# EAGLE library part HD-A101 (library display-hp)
LED DISPLAY 1-character 7 segment, decimal point right
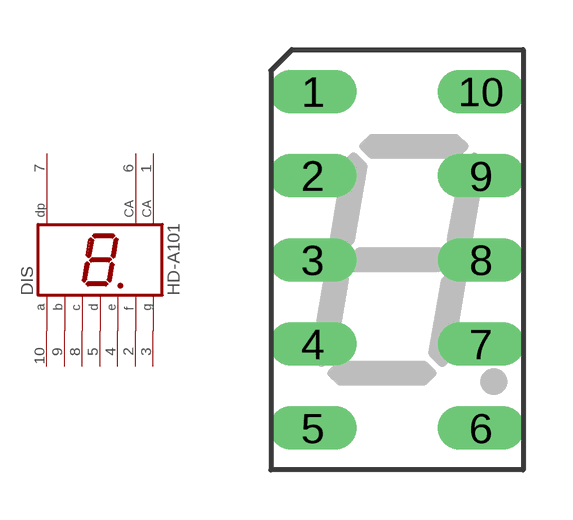
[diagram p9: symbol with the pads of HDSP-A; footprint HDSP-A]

Designator prefix DIS

## HD-A101 (OC_FARNELL: unknown; OC_NEWARK: unknown)  [HDSP-A]
1  CA  pas
2  F  pas
3  G  pas
4  E  pas
5  D  pas
6  CA  pas
7  DP  pas
8  C  pas
9  B  pas
10  A  pas

## Footprint HDSP-A (pad centres in mm)
LED DISPLAY 8-mm 1 character 7 segment, decimal point right
drill 0.813 long: 1 -2.54,5.08; 2 -2.54,2.54; 3 -2.54,0; 4 -2.54,-2.54; 5 -2.54,-5.08; 6 2.54,-5.08; 7 2.54,-2.54; 8 2.54,0; 9 2.54,2.54; 10 2.54,5.08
